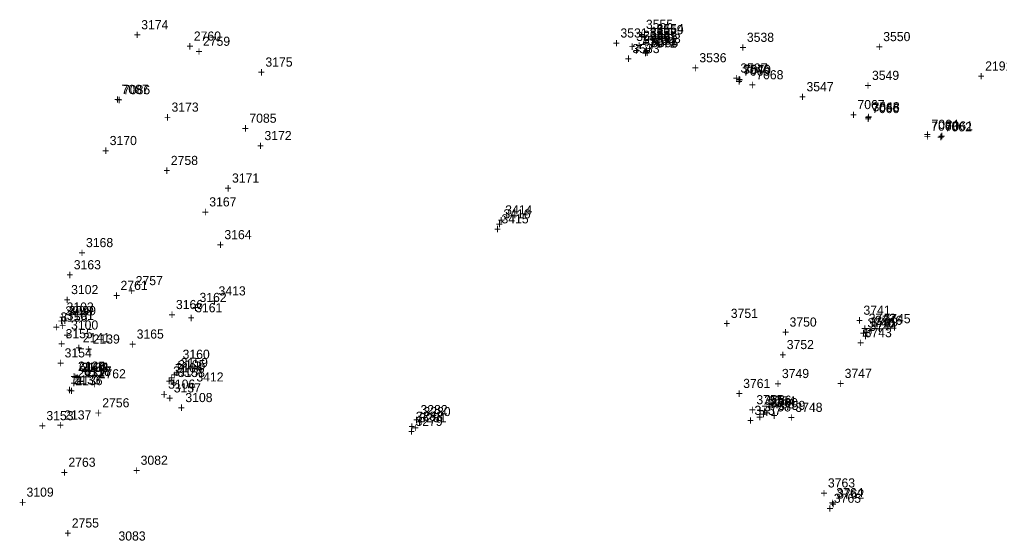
# Model space of a CAD drawing. Extents: x 1136220 to 1137808, y 528804 to 531215.
# Drawn here: x 1137069.6 to 1137337.9, y 529888.8 to 530031 of the extents above; entities that cross this region are included whole.
import ezdxf

# ---------------------------------------------------------------- set-up
doc = ezdxf.new("R2010")
doc.units = 0
for name, color, linetype in [('S_Annotation_Label', 7, 'Continuous'), ('S_Buildings', 7, 'Continuous'), ('S_Buildings_SillElevation', 7, 'Continuous'), ('S_Curb_Type_1', 7, 'Continuous'), ('S_Curb_Type_3', 7, 'Continuous'), ('S_Drainage_CB', 7, 'Continuous'), ('S_Drainage_Culvert_Top', 7, 'Continuous'), ('S_Drainage_Invert', 7, 'Continuous'), ('S_Drainage_MH', 7, 'Continuous'), ('S_Drainage_Sump', 7, 'Continuous'), ('S_Ground_Elevation', 7, 'Continuous'), ('S_Ground_SpotElevation', 7, 'Continuous'), ('S_Roadway_Centerline', 7, 'Continuous'), ('S_Roadway_Edge_Pavement', 7, 'Continuous'), ('S_Utilities_Pole_Joint', 7, 'Continuous'), ('S_Utilities_UG_Gas_Line', 7, 'Continuous'), ('S_Utilities_UG_Sanitary_MH', 7, 'Continuous'), ('S_Utilities_UG_Water_Gate', 7, 'Continuous'), ('S_Utilities_UG_Water_Line', 7, 'Continuous'), ('S_Utilities_UG_Water_Shutoff', 7, 'Continuous')]:
    doc.layers.add(name, color=color, linetype=linetype)

msp = doc.modelspace()

# ---------------------------------------------------------------- texts
at = {"layer": 'S_Annotation_Label'}
for s, p in [('3559', (1137243.98, 530026.98)), ('+', (1137241.92, 530024.23))]:
    msp.add_text(s, height=2.5, dxfattribs=at).set_placement(p)
at = {"layer": 'S_Buildings'}
for s, p in [('3413', (1137124.07, 529955.53)), ('+', (1137122.01, 529952.78)), ('3751', (1137264.35, 529949.37)), ('+', (1137262.29, 529946.62)), ('3750', (1137280.44, 529947)), ('+', (1137278.38, 529944.25)), ('3412', (1137118, 529931.98)), ('3749', (1137278.36, 529932.92)), ('+', (1137115.94, 529929.23)), ('+', (1137276.3, 529930.17))]:
    msp.add_text(s, height=2.5, dxfattribs=at).set_placement(p)
at = {"layer": 'S_Buildings_SillElevation'}
for s, p in [('3752', (1137279.68, 529940.84)), ('+', (1137277.62, 529938.09))]:
    msp.add_text(s, height=2.5, dxfattribs=at).set_placement(p)
at = {"layer": 'S_Curb_Type_1'}
for s, p in [('7069', (1137267.71, 530015.65)), ('7068', (1137271.33, 530014.67)), ('+', (1137265.65, 530012.9)), ('7087', (1137097.5, 530010.67)), ('+', (1137269.27, 530011.92)), ('+', (1137095.44, 530007.92)), ('7067', (1137299.04, 530006.51)), ('7066', (1137303.06, 530005.42)), ('+', (1137296.98, 530003.76)), ('+', (1137301, 530002.67)), ('7063', (1137319.25, 530000.61)), ('7062', (1137322.94, 530000.41)), ('+', (1137317.19, 529997.86)), ('+', (1137320.88, 529997.66))]:
    msp.add_text(s, height=2.5, dxfattribs=at).set_placement(p)
at = {"layer": 'S_Curb_Type_3'}
for s, p in [('7073', (1137239.63, 530024.08)), ('7072', (1137242.1, 530023.35)), ('+', (1137237.57, 530021.33)), ('+', (1137240.04, 530020.6))]:
    msp.add_text(s, height=2.5, dxfattribs=at).set_placement(p)
at = {"layer": 'S_Drainage_CB'}
for s, p in [('3557', (1137242.14, 530026.05)), ('+', (1137240.08, 530023.3)), ('3414', (1137202.57, 529977.69)), ('+', (1137200.51, 529974.94)), ('3098', (1137082.12, 529950.07)), ('+', (1137080.06, 529947.32)), ('3104', (1137112.3, 529934.51)), ('+', (1137110.24, 529931.76)), ('3753', (1137274.38, 529924.62)), ('+', (1137272.32, 529921.87)), ('3279', (1137177.99, 529919.82)), ('+', (1137175.93, 529917.07)), ('3762', (1137293.47, 529899.96)), ('+', (1137291.41, 529897.21))]:
    msp.add_text(s, height=2.5, dxfattribs=at).set_placement(p)
at = {"layer": 'S_Drainage_Culvert_Top'}
for s, p in [('2191', (1137334.02, 530017.07)), ('+', (1137331.95, 530014.32)), ('3415', (1137201.55, 529975.24)), ('+', (1137199.49, 529972.49)), ('3102', (1137083.7, 529955.89)), ('+', (1137081.64, 529953.14)), ('3741', (1137300.68, 529950.24)), ('3745', (1137306.14, 529947.92)), ('3100', (1137083.67, 529946.2)), ('+', (1137298.62, 529947.49)), ('+', (1137304.08, 529945.17)), ('+', (1137081.61, 529943.45)), ('2141', (1137086.9, 529942.74)), ('2139', (1137089.59, 529942.35)), ('3743', (1137301.01, 529944.1)), ('+', (1137084.83, 529939.99)), ('+', (1137298.95, 529941.35)), ('+', (1137087.53, 529939.6)), ('2140', (1137085.57, 529934.89)), ('2138', (1137086.44, 529934.6)), ('+', (1137083.51, 529932.14)), ('+', (1137084.38, 529931.85)), ('3747', (1137295.53, 529932.95)), ('2136', (1137084.86, 529930.97)), ('3106', (1137110.25, 529930.01)), ('+', (1137293.47, 529930.2)), ('+', (1137082.8, 529928.22)), ('+', (1137108.19, 529927.26)), ('3755', (1137271.36, 529925.74)), ('3759', (1137277.32, 529924.18)), ('3748', (1137282.03, 529923.67)), ('2137', (1137081.81, 529921.58)), ('3282', (1137179.38, 529923.03)), ('3280', (1137180.18, 529922.51)), ('+', (1137269.29, 529922.99)), ('3757', (1137270.83, 529922.83)), ('+', (1137275.26, 529921.43)), ('+', (1137279.97, 529920.92)), ('+', (1137079.75, 529918.83)), ('+', (1137177.32, 529920.28)), ('+', (1137178.12, 529919.76)), ('+', (1137268.77, 529920.08)), ('3763', (1137290.95, 529902.98)), ('+', (1137288.89, 529900.23))]:
    msp.add_text(s, height=2.5, dxfattribs=at).set_placement(p)
at = {"layer": 'S_Drainage_Invert'}
for s, p in [('3416', (1137202.08, 529976.61)), ('+', (1137200.02, 529973.86)), ('3103', (1137082.45, 529951.11)), ('+', (1137080.39, 529948.36)), ('3101', (1137082.48, 529948.8)), ('3742', (1137302.13, 529948.04)), ('3746', (1137303.88, 529947.47)), ('+', (1137080.42, 529946.05)), ('+', (1137300.07, 529945.29)), ('3744', (1137302.34, 529945.91)), ('+', (1137300.28, 529943.16)), ('+', (1137301.81, 529944.72)), ('2135', (1137085.56, 529934.93)), ('2134', (1137086.47, 529934.61)), ('+', (1137083.5, 529932.18)), ('+', (1137084.41, 529931.86)), ('3107', (1137111.64, 529933.6)), ('2133', (1137084.33, 529931.2)), ('+', (1137109.58, 529930.85)), ('+', (1137082.27, 529928.45)), ('3758', (1137273.38, 529923.79)), ('3756', (1137273.52, 529925.62)), ('3760', (1137275.3, 529924.94)), ('3283', (1137178.09, 529921.22)), ('3281', (1137179.04, 529920.85)), ('+', (1137271.32, 529921.04)), ('+', (1137271.46, 529922.87)), ('+', (1137273.24, 529922.19)), ('+', (1137176.03, 529918.47)), ('+', (1137176.98, 529918.1)), ('3764', (1137293.25, 529900.33)), ('+', (1137291.19, 529897.58))]:
    msp.add_text(s, height=2.5, dxfattribs=at).set_placement(p)
at = {"layer": 'S_Drainage_MH'}
for s, p in [('3739', (1137302.68, 529946.99)), ('+', (1137300.62, 529944.24))]:
    msp.add_text(s, height=2.5, dxfattribs=at).set_placement(p)
at = {"layer": 'S_Drainage_Sump'}
for s, p in [('3558', (1137242.2, 530026.3)), ('+', (1137240.14, 530023.55)), ('3099', (1137083.06, 529950.13)), ('+', (1137081, 529947.38)), ('3740', (1137301.77, 529946.78)), ('+', (1137299.71, 529944.03)), ('3105', (1137113.03, 529935.32)), ('+', (1137110.97, 529932.57)), ('3754', (1137274.63, 529925.45)), ('+', (1137272.57, 529922.7)), ('3765', (1137292.58, 529898.79)), ('+', (1137290.52, 529896.04))]:
    msp.add_text(s, height=2.5, dxfattribs=at).set_placement(p)
at = {"layer": 'S_Ground_Elevation'}
for s, p in [('3535', (1137242.52, 530023.46)), ('3538', (1137268.76, 530024.92)), ('+', (1137240.46, 530020.71)), ('+', (1137266.7, 530022.17)), ('3536', (1137255.74, 530019.32)), ('+', (1137253.68, 530016.57)), ('3537', (1137266.97, 530016.51)), ('3549', (1137303.02, 530014.5)), ('+', (1137264.91, 530013.76)), ('+', (1137300.96, 530011.75))]:
    msp.add_text(s, height=2.5, dxfattribs=at).set_placement(p)
at = {"layer": 'S_Ground_SpotElevation'}
for s, p in [('3555', (1137241.11, 530028.47)), ('+', (1137239.05, 530025.72)), ('3556', (1137240.34, 530025.46)), ('3554', (1137244.04, 530027.27)), ('+', (1137241.98, 530024.52)), ('3553', (1137243.2, 530024.59)), ('+', (1137238.27, 530022.71)), ('+', (1137241.14, 530021.84)), ('6116', (1137085.85, 529934.74)), ('+', (1137083.78, 529931.99)), ('6118', (1137087.18, 529933.47)), ('6117', (1137087.34, 529933.61)), ('+', (1137085.12, 529930.72)), ('+', (1137085.28, 529930.86))]:
    msp.add_text(s, height=2.5, dxfattribs=at).set_placement(p)
at = {"layer": 'S_Roadway_Centerline'}
for s, p in [('2759', (1137119.8, 530023.84)), ('3550', (1137306.1, 530025.11)), ('+', (1137117.74, 530021.09)), ('+', (1137304.04, 530022.36)), ('2758', (1137111, 529991.22)), ('+', (1137108.94, 529988.47)), ('2757', (1137101.38, 529958.34)), ('+', (1137099.31, 529955.59)), ('2756', (1137092.22, 529924.9)), ('+', (1137090.16, 529922.15)), ('2755', (1137083.88, 529892.02)), ('+', (1137081.82, 529889.27))]:
    msp.add_text(s, height=2.5, dxfattribs=at).set_placement(p)
at = {"layer": 'S_Roadway_Edge_Pavement'}
for s, p in [('3174', (1137102.89, 530028.36)), ('+', (1137100.83, 530025.61)), ('3531', (1137234.13, 530026.1)), ('+', (1137232.06, 530023.35)), ('7071', (1137242.18, 530023.94)), ('3532', (1137242.38, 530024.14)), ('+', (1137240.12, 530021.19)), ('+', (1137240.32, 530021.39)), ('3175', (1137136.9, 530018.14)), ('+', (1137134.84, 530015.39)), ('3546', (1137267.71, 530016.2)), ('7070', (1137267.91, 530016.06)), ('+', (1137265.65, 530013.45)), ('+', (1137265.85, 530013.31)), ('7086', (1137097.91, 530010.57)), ('3547', (1137285.08, 530011.4)), ('+', (1137095.85, 530007.82)), ('+', (1137283.01, 530008.65)), ('7065', (1137303.12, 530005.78)), ('3548', (1137303.18, 530005.9)), ('7085', (1137132.51, 530002.78)), ('+', (1137301.06, 530003.03)), ('+', (1137301.12, 530003.16)), ('7064', (1137319.3, 530001.11)), ('+', (1137130.45, 530000.03)), ('7061', (1137323.22, 530000.68)), ('3170', (1137094.26, 529996.67)), ('+', (1137317.23, 529998.36)), ('+', (1137321.16, 529997.93)), ('+', (1137092.2, 529993.92)), ('3171', (1137127.76, 529986.4)), ('+', (1137125.7, 529983.65)), ('3163', (1137084.42, 529962.68)), ('+', (1137082.36, 529959.93)), ('3162', (1137118.85, 529953.74)), ('+', (1137116.79, 529950.99)), ('3156', (1137080.74, 529948.38)), ('+', (1137078.68, 529945.63)), ('3155', (1137082.18, 529943.82)), ('+', (1137080.12, 529941.07)), ('3154', (1137081.91, 529938.57)), ('3160', (1137114.22, 529938.19)), ('+', (1137079.85, 529935.82)), ('+', (1137112.16, 529935.44)), ('3159', (1137113.71, 529935.88)), ('+', (1137111.65, 529933.13)), ('3158', (1137112.89, 529933.19)), ('+', (1137110.83, 529930.44)), ('3157', (1137111.8, 529928.98)), ('+', (1137109.74, 529926.23)), ('3153', (1137076.91, 529921.39)), ('+', (1137074.85, 529918.64)), ('3082', (1137102.73, 529909.19)), ('+', (1137100.67, 529906.44)), ('3109', (1137071.48, 529900.45)), ('+', (1137069.42, 529897.71)), ('3083', (1137096.66, 529888.46))]:
    msp.add_text(s, height=2.5, dxfattribs=at).set_placement(p)
at = {"layer": 'S_Utilities_Pole_Joint'}
for s, p in [('3164', (1137125.67, 529970.92)), ('+', (1137123.61, 529968.17))]:
    msp.add_text(s, height=2.5, dxfattribs=at).set_placement(p)
at = {"layer": 'S_Utilities_UG_Gas_Line'}
for s, p in [('3167', (1137121.53, 529979.89)), ('+', (1137119.46, 529977.14)), ('3168', (1137087.77, 529968.74)), ('+', (1137085.71, 529965.99)), ('3166', (1137112.4, 529951.79)), ('+', (1137110.34, 529949.04)), ('3165', (1137101.64, 529943.71)), ('+', (1137099.58, 529940.96))]:
    msp.add_text(s, height=2.5, dxfattribs=at).set_placement(p)
at = {"layer": 'S_Utilities_UG_Sanitary_MH'}
for s, p in [('2132', (1137085.52, 529933.1)), ('+', (1137083.46, 529930.35)), ('3761', (1137267.74, 529930.2)), ('+', (1137265.68, 529927.45))]:
    msp.add_text(s, height=2.5, dxfattribs=at).set_placement(p)
at = {"layer": 'S_Utilities_UG_Water_Gate'}
for s, p in [('2760', (1137117.3, 530025.25)), ('+', (1137115.24, 530022.5))]:
    msp.add_text(s, height=2.5, dxfattribs=at).set_placement(p)
at = {"layer": 'S_Utilities_UG_Water_Line'}
for s, p in [('3534', (1137238.44, 530025.15)), ('+', (1137236.38, 530022.4)), ('3173', (1137111.18, 530005.81)), ('+', (1137109.12, 530003.06)), ('3172', (1137136.64, 529998.03)), ('+', (1137134.58, 529995.28)), ('2761', (1137097.22, 529957.03)), ('+', (1137095.16, 529954.28)), ('2762', (1137091.24, 529932.84)), ('+', (1137089.18, 529930.09)), ('3108', (1137114.98, 529926.34)), ('+', (1137112.92, 529923.59)), ('2763', (1137082.95, 529908.64)), ('+', (1137080.89, 529905.89))]:
    msp.add_text(s, height=2.5, dxfattribs=at).set_placement(p)
at = {"layer": 'S_Utilities_UG_Water_Shutoff'}
for s, p in [('3533', (1137237.4, 530021.84)), ('+', (1137235.34, 530019.09)), ('3161', (1137117.66, 529950.91)), ('+', (1137115.6, 529948.16))]:
    msp.add_text(s, height=2.5, dxfattribs=at).set_placement(p)

doc.saveas('drawing.dxf')
